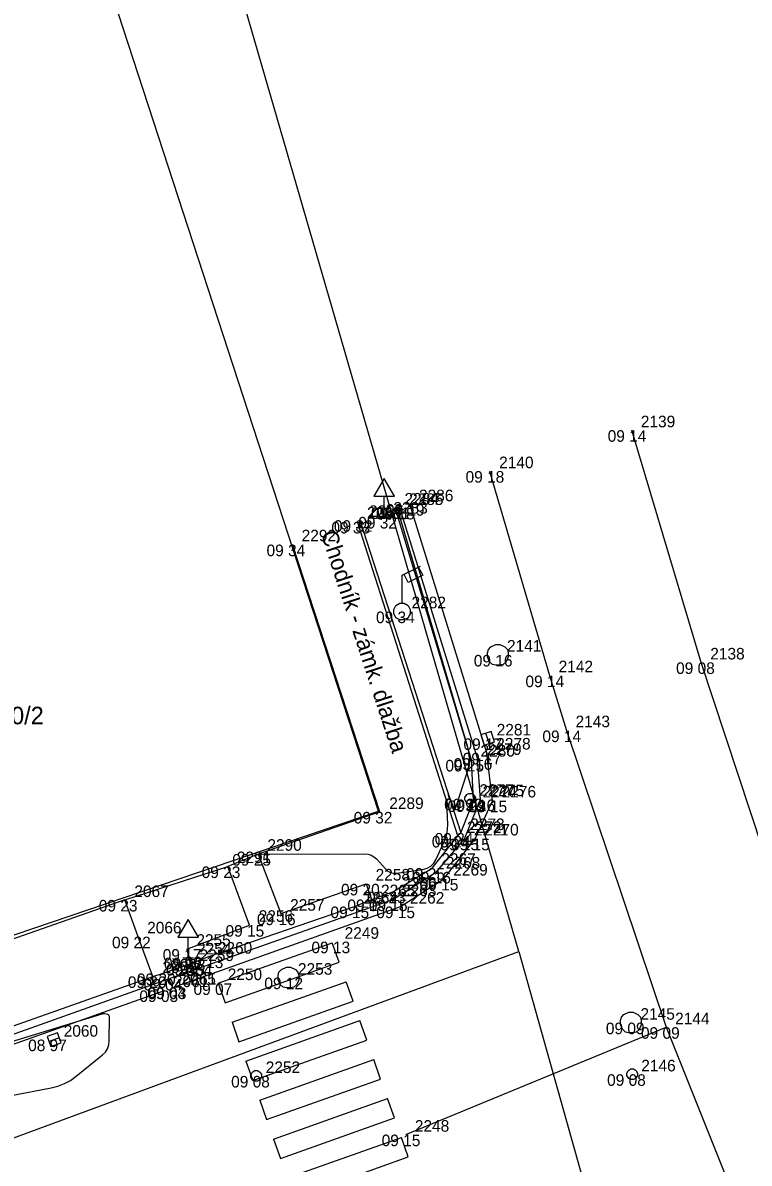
# Model space of a CAD drawing. Extents: x -703403 to -701924, y -1022520 to -1021856.
# Drawn here: x -702873.38 to -702855.8, y -1021953.17 to -1021925.57 of the extents above; entities that cross this region are included whole.
import ezdxf

# ---------------------------------------------------------------- set-up
doc = ezdxf.new("R2010")
doc.units = 0
for name, color, linetype in [('Ex_Major Contours', 7, 'Continuous'), ('Ex_Minor Contours', 7, 'Continuous'), ('Z_body', 7, 'Continuous'), ('Z_body_cisla', 7, 'Continuous'), ('Z_body_vysky_redukovane', 7, 'Continuous'), ('Z_budova', 7, 'Continuous'), ('Z_chodnik', 7, 'Continuous'), ('Z_dopravni_znacky', 7, 'Continuous'), ('Z_katastr_cisla_stavebni', 7, 'Continuous'), ('Z_katastr_hranice', 7, 'Continuous'), ('Z_komunikace', 7, 'Continuous'), ('Z_komunikace_osa', 7, 'Continuous'), ('Z_obruba', 7, 'Continuous'), ('Z_popisy', 7, 'Continuous'), ('Z_rozhranni', 7, 'Continuous'), ('Z_site_kanalizace_znaky', 7, 'Continuous'), ('Z_site_plynovod_znaky', 7, 'Continuous'), ('Z_site_vo_znaky', 7, 'Continuous'), ('Z_site_vodovod_znaky', 7, 'Continuous'), ('Z_vdz13_prerusovana', 7, 'Continuous'), ('Z_VDZ25_zluta', 7, 'Continuous'), ('Z_VDZ_25_plna', 7, 'Continuous'), ('Z_VDZ_25_prerus', 7, 'Continuous'), ('Z_vdz_prechod', 7, 'Continuous')]:
    doc.layers.add(name, color=color, linetype=linetype)

# ---------------------------------------------------------------- blocks, each defined once
blk = doc.blocks.new('POINT_DISPLAY')
blk.add_line((0, 0), (0, 0))
blk = doc.blocks.new('Z614')
for p, q in [((-0.13, 0.03), (-0.1, 0.08)), ((-0.13, -0.03), (-0.13, 0.03)), ((-0.1, 0.08), (-0.08, 0.1)), ((-0.08, 0.1), (-0.03, 0.13)), ((-0.03, 0.13), (0.03, 0.13)), ((0.03, 0.13), (0.08, 0.1)), ((0.08, 0.1), (0.1, 0.08)), ((0.1, 0.08), (0.13, 0.03)), ((0.13, 0.03), (0.13, -0.03)), ((-0.1, -0.08), (-0.13, -0.03)), ((-0.08, -0.1), (-0.1, -0.08)), ((-0.03, -0.13), (-0.08, -0.1)), ((0.03, -0.13), (-0.03, -0.13)), ((0.08, -0.1), (0.03, -0.13)), ((0.1, -0.08), (0.08, -0.1)), ((0.13, -0.03), (0.1, -0.08))]:
    blk.add_line(p, q)
blk = doc.blocks.new('Z13')
for p, q in [((0, 0.88), (0.45, 1.1)), ((0, 0.2), (0, 0.88)), ((0.15, 0.7), (0.05, 0.9)), ((0.5, 0.88), (0.15, 0.7)), ((0.4, 1.07), (0.5, 0.88)), ((-0.2, 0.05), (-0.15, 0.15)), ((-0.2, -0.05), (-0.2, 0.05)), ((-0.15, 0.15), (-0.05, 0.2)), ((-0.05, 0.2), (0.05, 0.2)), ((0.05, 0.2), (0.15, 0.15)), ((0.15, 0.15), (0.2, 0.05)), ((0.2, 0.05), (0.2, -0.05)), ((-0.15, -0.15), (-0.2, -0.05)), ((-0.05, -0.2), (-0.15, -0.15)), ((0.05, -0.2), (-0.05, -0.2)), ((0.15, -0.15), (0.05, -0.2)), ((0.2, -0.05), (0.15, -0.15))]:
    blk.add_line(p, q)
blk = doc.blocks.new('Z620')
for p, q in [((-0.25, 0.05), (-0.23, 0.13)), ((-0.25, -0.05), (-0.25, 0.05)), ((-0.23, 0.13), (-0.17, 0.2)), ((-0.17, 0.2), (-0.05, 0.25)), ((-0.05, 0.25), (0.05, 0.25)), ((0.05, 0.25), (0.17, 0.2)), ((0.17, 0.2), (0.23, 0.13)), ((0.23, 0.13), (0.25, 0.05)), ((0.25, 0.05), (0.25, -0.05)), ((-0.2, -0.17), (-0.25, -0.05)), ((-0.13, -0.23), (-0.2, -0.17)), ((-0.05, -0.25), (-0.13, -0.23)), ((0.05, -0.25), (-0.05, -0.25)), ((0.13, -0.23), (0.05, -0.25)), ((0.2, -0.17), (0.13, -0.23)), ((0.25, -0.05), (0.2, -0.17))]:
    blk.add_line(p, q)
blk = doc.blocks.new('Z46260')
for p, q in [((0.13, 0.13), (-0.13, 0.13)), ((-0.13, 0.13), (-0.13, -0.13)), ((0.13, 0), (-0.13, 0)), ((0.13, -0.13), (0.13, 0.13)), ((-0.13, -0.13), (0.13, -0.13))]:
    blk.add_line(p, q)
blk = doc.blocks.new('Z527')
for p, q in [((0, 0.93), (-0.25, 0.5)), ((0.25, 0.5), (0, 0.93)), ((-0.25, 0.5), (0.25, 0.5)), ((0, 0), (0, 0.5)), ((-0.13, 0), (0.13, 0))]:
    blk.add_line(p, q)

msp = doc.modelspace()

# ---------------------------------------------------------------- linework, layer by layer
at = {"layer": 'Ex_Major Contours'}
msp.add_lwpolyline([(-702873.698, -1021951.542), (-702872.694, -1021951.349), (-702872.529, -1021951.307), (-702872.374, -1021951.246), (-702872.227, -1021951.167), (-702872.089, -1021951.068), (-702871.449, -1021950.551), (-702871.378, -1021950.481), (-702871.327, -1021950.401), (-702871.296, -1021950.311), (-702871.286, -1021950.211), (-702871.285, -1021949.623), (-702871.287, -1021949.606), (-702871.294, -1021949.592), (-702871.306, -1021949.582), (-702871.322, -1021949.576), (-702871.396, -1021949.559), (-702871.414, -1021949.556), (-702871.433, -1021949.555), (-702871.451, -1021949.557), (-702871.469, -1021949.561), (-702877.036, -1021951.269)], dxfattribs=at)
at = {"layer": 'Ex_Minor Contours'}
msp.add_lwpolyline([(-702867.68, -1021945.69), (-702865.097, -1021945.685), (-702865.018, -1021945.693), (-702864.946, -1021945.715), (-702864.881, -1021945.753), (-702864.822, -1021945.807), (-702864.601, -1021946.05), (-702864.543, -1021946.101), (-702864.478, -1021946.135), (-702864.407, -1021946.151), (-702864.329, -1021946.149), (-702863.702, -1021946.062), (-702863.594, -1021946.035), (-702863.504, -1021945.985), (-702863.431, -1021945.912), (-702863.374, -1021945.817), (-702863.166, -1021945.354), (-702863.131, -1021945.265), (-702863.108, -1021945.173), (-702863.096, -1021945.08), (-702863.095, -1021944.985), (-702863.119, -1021944.428), (-702863.118, -1021944.417), (-702863.116, -1021944.407), (-702863.111, -1021944.398), (-702863.104, -1021944.39), (-702863.073, -1021944.359), (-702863.067, -1021944.351), (-702863.063, -1021944.342), (-702863.062, -1021944.332), (-702863.063, -1021944.322), (-702863.078, -1021944.261), (-702863.081, -1021944.251), (-702863.081, -1021944.247), (-702863.079, -1021944.25), (-702863.075, -1021944.26), (-702862.963, -1021944.541), (-702862.943, -1021944.58), (-702862.924, -1021944.592), (-702862.905, -1021944.579), (-702862.888, -1021944.539), (-702862.621, -1021943.719), (-702862.582, -1021943.564), (-702862.568, -1021943.409), (-702862.578, -1021943.254), (-702862.611, -1021943.099), (-702864.315, -1021937.305)], dxfattribs=at)
at = {"layer": 'Z_budova'}
for p, q in [((-702864.74, -1021944.67), (-702866.85, -1021938.2)), ((-702864.74, -1021944.67), (-702867.68, -1021945.69)), ((-702867.68, -1021945.69), (-702868.42, -1021945.99)), ((-702870.91, -1021946.8), (-702868.42, -1021945.99)), ((-702870.91, -1021946.8), (-702884.26, -1021951.46))]:
    msp.add_line(p, q, dxfattribs=at)
at = {"layer": 'Z_chodnik'}
msp.add_line((-702862.85, -1021945.25), (-702865.28, -1021937.65), dxfattribs=at)
at = {"layer": 'Z_katastr_hranice'}
for p, q in [((-702861.37, -1021948.05), (-702872.98, -1021908.05)), ((-702864.77, -1021944.65), (-702872.85, -1021919.88)), ((-702877.91, -1021949.11), (-702864.77, -1021944.65)), ((-702894.96, -1021960.43), (-702861.37, -1021948.05)), ((-702861.37, -1021948.05), (-702859.3, -1021955.41))]:
    msp.add_line(p, q, dxfattribs=at)
at = {"layer": 'Z_komunikace'}
for p, q in [((-702862.37, -1021943.37), (-702864.25, -1021937.31)), ((-702862.3, -1021944.37), (-702862.37, -1021943.37)), ((-702862.69, -1021945.32), (-702862.3, -1021944.37)), ((-702863.37, -1021946.12), (-702862.69, -1021945.32)), ((-702864.42, -1021946.79), (-702863.37, -1021946.12)), ((-702869.85, -1021948.71), (-702864.42, -1021946.79)), ((-702877.07, -1021951.28), (-702869.85, -1021948.71))]:
    msp.add_line(p, q, dxfattribs=at)
at = {"layer": 'Z_komunikace_osa'}
msp.add_line((-702864.11, -1021952.48), (-702857.81, -1021949.88), dxfattribs=at)
at = {"layer": 'Z_obruba'}
for p, q in [((-702862.52, -1021943.41), (-702864.37, -1021937.3)), ((-702865.22, -1021937.61), (-702862.78, -1021945.18)), ((-702862.47, -1021944.39), (-702862.52, -1021943.41)), ((-702862.78, -1021945.18), (-702862.47, -1021944.39)), ((-702863.47, -1021946.03), (-702862.85, -1021945.25)), ((-702862.85, -1021945.25), (-702862.78, -1021945.18)), ((-702864.42, -1021946.6), (-702863.47, -1021946.03)), ((-702864.94, -1021946.79), (-702864.42, -1021946.6)), ((-702868.88, -1021948.17), (-702865.35, -1021946.96)), ((-702865.35, -1021946.96), (-702864.94, -1021946.79)), ((-702870.01, -1021948.58), (-702869.33, -1021948.35)), ((-702869.33, -1021948.35), (-702868.88, -1021948.17)), ((-702877.18, -1021951.12), (-702870.23, -1021948.65)), ((-702870.23, -1021948.65), (-702870.01, -1021948.58))]:
    msp.add_line(p, q, dxfattribs=at)
at = {"layer": 'Z_rozhranni'}
for p, q in [((-702862.15, -1021943.24), (-702864.01, -1021937.22)), ((-702862.01, -1021944.4), (-702862.15, -1021943.24)), ((-702862.43, -1021945.32), (-702862.01, -1021944.4)), ((-702863.19, -1021946.29), (-702862.43, -1021945.32)), ((-702867.68, -1021945.69), (-702867.13, -1021947.13)), ((-702867.89, -1021947.41), (-702868.42, -1021945.99)), ((-702867.13, -1021947.13), (-702865.07, -1021946.41)), ((-702865.07, -1021946.41), (-702864.94, -1021946.79)), ((-702864.24, -1021946.96), (-702863.19, -1021946.29)), ((-702870.59, -1021947.69), (-702870.91, -1021946.8)), ((-702869.75, -1021948.92), (-702864.24, -1021946.96)), ((-702869.41, -1021947.99), (-702867.89, -1021947.41)), ((-702870.23, -1021948.65), (-702870.59, -1021947.69)), ((-702869.41, -1021947.99), (-702869.33, -1021948.35)), ((-702869.85, -1021948.71), (-702869.76, -1021948.92))]:
    msp.add_line(p, q, dxfattribs=at)
at = {"layer": 'Z_vdz13_prerusovana'}
for p, q in [((-702856.96, -1021941.05), (-702858.64, -1021935.43)), ((-702854.58, -1021948.28), (-702856.96, -1021941.05))]:
    msp.add_line(p, q, dxfattribs=at)
at = {"layer": 'Z_VDZ25_zluta'}
msp.add_line((-702876.79, -1021951.42), (-702869.95, -1021948.99), dxfattribs=at)
at = {"layer": 'Z_VDZ_25_plna'}
msp.add_line((-702862.08, -1021936.42), (-702860.63, -1021941.37), dxfattribs=at)
at = {"layer": 'Z_VDZ_25_prerus'}
for p, q in [((-702860.63, -1021941.37), (-702860.22, -1021942.7)), ((-702860.22, -1021942.7), (-702857.81, -1021949.88)), ((-702857.81, -1021949.88), (-702854.75, -1021957.52))]:
    msp.add_line(p, q, dxfattribs=at)
at = {"layer": 'Z_vdz_prechod'}
for p, q in [((-702868.649, -1021948.818), (-702865.889, -1021947.838)), ((-702865.721, -1021948.309), (-702865.889, -1021947.838)), ((-702868.481, -1021949.289), (-702865.721, -1021948.309)), ((-702868.649, -1021948.818), (-702868.481, -1021949.289)), ((-702868.314, -1021949.76), (-702865.554, -1021948.78)), ((-702865.387, -1021949.251), (-702865.554, -1021948.78)), ((-702868.147, -1021950.231), (-702865.387, -1021949.251)), ((-702868.314, -1021949.76), (-702868.314, -1021949.76)), ((-702868.314, -1021949.76), (-702868.147, -1021950.231)), ((-702867.98, -1021950.702), (-702865.22, -1021949.722)), ((-702865.052, -1021950.193), (-702865.22, -1021949.722)), ((-702867.812, -1021951.173), (-702865.052, -1021950.193)), ((-702867.98, -1021950.702), (-702867.812, -1021951.173)), ((-702867.645, -1021951.645), (-702864.885, -1021950.665)), ((-702864.718, -1021951.136), (-702864.885, -1021950.665)), ((-702867.478, -1021952.116), (-702864.718, -1021951.136)), ((-702867.645, -1021951.645), (-702867.478, -1021952.116)), ((-702867.31, -1021952.587), (-702864.55, -1021951.607)), ((-702864.383, -1021952.078), (-702864.55, -1021951.607)), ((-702867.143, -1021953.058), (-702864.383, -1021952.078)), ((-702866.976, -1021953.529), (-702864.216, -1021952.549)), ((-702864.048, -1021953.021), (-702864.216, -1021952.549)), ((-702867.31, -1021952.587), (-702867.143, -1021953.058)), ((-702866.808, -1021954.001), (-702864.048, -1021953.021))]:
    msp.add_line(p, q, dxfattribs=at)

# ---------------------------------------------------------------- block references
at = {"layer": 'Z_body'}
for p in [(-702858.64, -1021935.43), (-702862.08, -1021936.42), (-702864.37, -1021937.3), (-702864.25, -1021937.31), (-702864.01, -1021937.22), (-702865.28, -1021937.65), (-702865.22, -1021937.61), (-702864.63, -1021937.53), (-702866.85, -1021938.2), (-702864.2, -1021939.82), (-702861.88, -1021940.87), (-702856.96, -1021941.05), (-702860.63, -1021941.37), (-702862.13, -1021942.89), (-702860.22, -1021942.7), (-702862.52, -1021943.41), (-702862.37, -1021943.37), (-702862.15, -1021943.24), (-702862.55, -1021944.35), (-702862.47, -1021944.39), (-702862.3, -1021944.37), (-702862.01, -1021944.4), (-702864.74, -1021944.67), (-702862.85, -1021945.25), (-702862.78, -1021945.18), (-702862.69, -1021945.32), (-702862.43, -1021945.32), (-702867.68, -1021945.69), (-702868.42, -1021945.99), (-702863.47, -1021946.03), (-702863.37, -1021946.12), (-702865.07, -1021946.41), (-702863.19, -1021946.29), (-702864.42, -1021946.6), (-702870.91, -1021946.8), (-702865.35, -1021946.96), (-702864.94, -1021946.79), (-702864.42, -1021946.79), (-702864.24, -1021946.96), (-702867.13, -1021947.13), (-702867.89, -1021947.41), (-702870.59, -1021947.69), (-702865.81, -1021947.81), (-702869.41, -1021947.99), (-702869.38, -1021948.2), (-702869.33, -1021948.35), (-702868.88, -1021948.17), (-702870.23, -1021948.65), (-702870.01, -1021948.58), (-702866.95, -1021948.68), (-702869.85, -1021948.71), (-702869.76, -1021948.92), (-702869.75, -1021948.92), (-702868.64, -1021948.82), (-702869.95, -1021948.99), (-702858.66, -1021949.77), (-702857.81, -1021949.88), (-702872.62, -1021950.18), (-702867.73, -1021951.06), (-702858.63, -1021951.02), (-702864.11, -1021952.48)]:
    msp.add_blockref('POINT_DISPLAY', p, dxfattribs=at)
at = {"layer": 'Z_dopravni_znacky'}
for p in [(-702864.63, -1021937.53), (-702869.38, -1021948.2)]:
    msp.add_blockref('Z527', p, dxfattribs=at)
at = {"layer": 'Z_site_kanalizace_znaky'}
for p in [(-702861.88, -1021940.87), (-702866.95, -1021948.68), (-702858.66, -1021949.77)]:
    msp.add_blockref('Z620', p, dxfattribs=at)
for p, rotation in [((-702862.13, -1021942.89), -72.00000000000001), ((-702872.62, -1021950.18), 19.8)]:
    msp.add_blockref('Z46260', p, dxfattribs=dict(at, rotation=rotation))
at = {"layer": 'Z_site_plynovod_znaky'}
for p in [(-702862.55, -1021944.35), (-702867.73, -1021951.06)]:
    msp.add_blockref('Z614', p, dxfattribs=at)
at = {"layer": 'Z_site_vo_znaky'}
msp.add_blockref('Z13', (-702864.2, -1021939.82), dxfattribs=at)
at = {"layer": 'Z_site_vodovod_znaky'}
msp.add_blockref('Z614', (-702858.63, -1021951.02), dxfattribs=at)

# ---------------------------------------------------------------- texts
at = {"layer": 'Z_body_cisla'}
for s, p in [('2139', (-702858.42, -1021935.36)), ('2140', (-702861.85, -1021936.35)), ('2284', (-702864.14, -1021937.23)), ('2285', (-702864.03, -1021937.24)), ('2286', (-702863.79, -1021937.15)), ('2288', (-702865.05, -1021937.57)), ('2287', (-702865, -1021937.53)), ('2283', (-702864.41, -1021937.45)), ('2292', (-702866.63, -1021938.12)), ('2282', (-702863.97, -1021939.74)), ('2141', (-702861.66, -1021940.79)), ('2138', (-702856.74, -1021940.98)), ('2142', (-702860.41, -1021941.29)), ('2143', (-702860, -1021942.62)), ('2281', (-702861.91, -1021942.82)), ('2278', (-702861.92, -1021943.16)), ('2280', (-702862.3, -1021943.33)), ('2279', (-702862.14, -1021943.29)), ('2277', (-702862.33, -1021944.28)), ('2274', (-702862.25, -1021944.32)), ('2275', (-702862.08, -1021944.29)), ('2276', (-702861.79, -1021944.32)), ('2289', (-702864.51, -1021944.6)), ('2273', (-702862.55, -1021945.11)), ('2272', (-702862.63, -1021945.18)), ('2271', (-702862.46, -1021945.24)), ('2270', (-702862.21, -1021945.24)), ('2290', (-702867.46, -1021945.61)), ('2291', (-702868.2, -1021945.91)), ('2267', (-702863.25, -1021945.95)), ('2268', (-702863.14, -1021946.04)), ('2269', (-702862.96, -1021946.21)), ('2258', (-702864.84, -1021946.33)), ('2067', (-702870.68, -1021946.73)), ('2265', (-702864.71, -1021946.71)), ('2266', (-702864.2, -1021946.53)), ('2263', (-702864.2, -1021946.71)), ('2264', (-702865.13, -1021946.89)), ('2262', (-702864.01, -1021946.89)), ('2257', (-702866.91, -1021947.06)), ('2256', (-702867.67, -1021947.33)), ('2066', (-702870.37, -1021947.61)), ('2249', (-702865.59, -1021947.74)), ('2255', (-702869.18, -1021947.91)), ('2254', (-702869.16, -1021948.12)), ('2260', (-702868.66, -1021948.1)), ('2259', (-702869.1, -1021948.28)), ('2062', (-702870, -1021948.57)), ('2063', (-702869.79, -1021948.51)), ('2064', (-702869.63, -1021948.64)), ('2253', (-702866.72, -1021948.61)), ('2061', (-702869.72, -1021948.91)), ('2065', (-702869.54, -1021948.85)), ('2261', (-702869.53, -1021948.85)), ('2250', (-702868.42, -1021948.74)), ('2145', (-702858.43, -1021949.7)), ('2144', (-702857.59, -1021949.81)), ('2060', (-702872.39, -1021950.11)), ('2252', (-702867.5, -1021950.99)), ('2146', (-702858.41, -1021950.95)), ('2248', (-702863.89, -1021952.41))]:
    msp.add_text(s, height=0.28, dxfattribs=at).set_placement(p)
at = {"layer": 'Z_body_vysky_redukovane'}
for s, p in [('09 14', (-702859.223, -1021935.71)), ('09 18', (-702862.663, -1021936.7)), ('09 31', (-702864.953, -1021937.58)), ('09 18', (-702864.833, -1021937.59)), ('09 19', (-702864.593, -1021937.5)), ('09 33', (-702865.91, -1021937.93)), ('09 32', (-702865.85, -1021937.89)), ('09 32', (-702865.26, -1021937.81)), ('09 34', (-702867.48, -1021938.48)), ('09 34', (-702864.83, -1021940.1)), ('09 16', (-702862.463, -1021941.15)), ('09 08', (-702857.567, -1021941.33)), ('09 14', (-702861.213, -1021941.65)), ('09 17', (-702862.713, -1021943.17)), ('09 14', (-702860.803, -1021942.98)), ('09 25', (-702863.15, -1021943.69)), ('09 16', (-702862.953, -1021943.65)), ('09 17', (-702862.733, -1021943.52)), ('09 23', (-702863.18, -1021944.63)), ('09 23', (-702863.1, -1021944.67)), ('09 16', (-702862.883, -1021944.65)), ('09 15', (-702862.593, -1021944.68)), ('09 32', (-702865.37, -1021944.95)), ('09 24', (-702863.48, -1021945.53)), ('09 24', (-702863.41, -1021945.46)), ('09 15', (-702863.273, -1021945.6)), ('09 15', (-702863.013, -1021945.6)), ('09 25', (-702868.31, -1021945.97)), ('09 23', (-702869.05, -1021946.27)), ('09 25', (-702864.1, -1021946.31)), ('09 16', (-702863.953, -1021946.4)), ('09 20', (-702865.677, -1021946.69)), ('09 15', (-702863.773, -1021946.57)), ('09 23', (-702865.05, -1021946.88)), ('09 23', (-702871.54, -1021947.08)), ('09 15', (-702865.933, -1021947.24)), ('09 19', (-702865.523, -1021947.07)), ('09 15', (-702865.003, -1021947.07)), ('09 15', (-702864.823, -1021947.24)), ('09 16', (-702867.713, -1021947.41)), ('09 15', (-702868.473, -1021947.69)), ('09 22', (-702871.22, -1021947.97)), ('09 13', (-702866.393, -1021948.09)), ('09 17', (-702869.993, -1021948.27)), ('09 17', (-702869.963, -1021948.48)), ('09 15', (-702869.913, -1021948.63)), ('09 13', (-702869.463, -1021948.45)), ('09 20', (-702870.837, -1021948.93)), ('09 20', (-702870.617, -1021948.86)), ('09 12', (-702867.533, -1021948.96)), ('09 04', (-702870.457, -1021948.99)), ('09 04', (-702870.367, -1021949.2)), ('09 03', (-702870.357, -1021949.2)), ('09 07', (-702869.247, -1021949.1)), ('09 03', (-702870.557, -1021949.27)), ('09 09', (-702859.267, -1021950.05)), ('09 09', (-702858.417, -1021950.16)), ('08 97', (-702873.25, -1021950.46)), ('09 08', (-702868.337, -1021951.34)), ('09 08', (-702859.237, -1021951.3)), ('09 15', (-702864.693, -1021952.76))]:
    msp.add_text(s, height=0.28, dxfattribs=at).set_placement(p)
at = {"layer": 'Z_katastr_cisla_stavebni'}
msp.add_text('60/2', height=0.425, dxfattribs=at).set_placement((-702873.978, -1021942.549))
at = {"layer": 'Z_popisy'}
msp.add_text('Chodník - zámk. dlažba', height=0.4, rotation=288, dxfattribs=at).set_placement((-702866.17, -1021937.93))

doc.saveas('drawing.dxf')
